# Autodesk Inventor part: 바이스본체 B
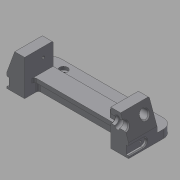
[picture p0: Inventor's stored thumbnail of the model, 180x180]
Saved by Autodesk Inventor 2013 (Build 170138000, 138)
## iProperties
Created: 2017-04
Part Number: 바이스본체 B
Material: 일반
Document SubType Name: Modeling
Designer: mduedu
Density: 1 g/cm^3
Mass: 119.615 g
Surface Area: 275.767 cm^2
Volume: 119.615 cm^3
Author: mduedu
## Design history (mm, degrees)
sketch "스케치1"
  geometry: L1 (-75, 0)-(75, 0); L2 (-75, 0)-(-75, 17); L3 (-53, 17)-(53, 17); L4 (75, 17)-(75, 0); L5 (-75, 17)-(-65.173, 44); L6 (-65.173, 44)-(-53, 44); L7 (-53, 44)-(-53, 17); L8 (0, 0)-(0, 17); L9 (75, 17)-(65.173, 44); L10 (65.173, 44)-(53, 44); L11 (53, 44)-(53, 17); 1 further point
  constraints: 22 end point, 4 perpendicular, 2 horizontal alignment, 2 midpoint, 2 symmetric about line, 1 coincident, 1 collinear, 1 horizontal, 1 vertical
  dimensions: "d0" = 150 distance of L1.start L1.end; "d1" = 17 distance of L1.start L2.end; "d2" = 27 distance of L3.start L6.end; "d3" = 22 distance of L3.start L2.end; "d4" = 70 deg angle of L3 L5; "d54" = 20 deg angle of L9 L4
extrude "돌출1" new body sketch "스케치1" stored distance "d5" = 70; taper "d6" = 0 deg
sketch "스케치2"
  geometry: L1 (0, 70)-(106, 70) reference; L2 (106, 70)-(106, 0) reference; L3 (106, 0)-(0, 0) reference; L4 (0, 47)-(106, 47); L5 (106, 47)-(106, 23); L6 (106, 23)-(0, 23); L7 (0, 23)-(0, 47); L8 (0, 70)-(0, 0) reference; 2 further points
  constraints: 8 end point, 2 parallel, 2 point on line, 1 horizontal, 1 horizontal alignment, 1 midpoint, 1 perpendicular
  dimensions: "d7" = 24 distance between parallel lines of L6 L4
extrude "돌출2" cut sketch "스케치2" stored distance "d9" = 70; taper "d10" = 0 deg
sketch "스케치3"
  geometry: L1 (22, -23)-(128, -23) reference; L2 (128, -47)-(22, -47) reference; L3 (22, -18)-(128, -18); L4 (128, -52)-(22, -52); L5 (22, -18)-(22, -52); L6 (128, -18)-(128, -52); 1 further point
  constraints: 8 end point, 3 parallel, 2 point on line, 1 perpendicular
  dimensions: "d11" = 5 distance between parallel lines of L3 L1; "d12" = 5 distance between parallel lines of L4 L2
extrude "돌출3" cut sketch "스케치3" distance "d13" = 12; taper "d14" = 0 deg
fillet "모깎기1" dims "d15" = 3, "d16" = 3
sketch "스케치4"
  geometry: L1 (103, 23)-(3, 23) reference; L2 (0, 26)-(0, 0) reference; L3 (106, 0)-(0, 0) reference; L4 (106, 26)-(106, 0) reference; L5 (96, 0)-(90, 0); L6 (90, 0)-(90, 19.5); L7 (96, 19.5)-(96, 0); L8 (90, 19.5)-(96, 19.5); A1 r 3 centre (3, 26) between (0, 26) and (3, 23) reference; A2 r 3 centre (103, 26) between (103, 23) and (106, 26) reference; 1 further point
  constraints: 8 end point, 2 perpendicular, 1 horizontal, 1 parallel, 1 point on line
  dimensions: "d17" = 10 distance between parallel lines of L7 L4; "d18" = 6 distance between parallel lines of L7 L6; "d27" = 3.5 distance between parallel lines of L8 L1
extrude "돌출4" join sketch "스케치4" distance "d19" = 12; taper "d20" = 0 deg
chamfer "모따기1" distance "d21" = 3; stored, may be unused: second distance "d22" = 2, angle "d23" = 45 deg
chamfer "모따기2" distance "d24" = 3; stored, may be unused: second distance "d25" = 2, angle "d26" = 45 deg
sketch "스케치5"
  geometry: L1 (-15.5, 35.8)-(-15.5, -25.8) reference; L2 (19.5, 0)-(0, 0) reference; C1 r 6.5 at (9.5, 15); 1 further point
  constraints: 1 centre point
  dimensions: "d28" = 13 diameter of C1; "d30" = 15 distance from line of C1.centre L2; "d31" = 25 distance from line of C1.centre L1
extrude "돌출5" cut sketch "스케치5" stored distance "d32" = 12; taper "d33" = 0 deg
sketch "스케치6"
  geometry: C1 r 5 at (-10, 15); C2 r 5 at (-60, 15); A1 r 6.5 centre (-10, 15) between (-15.766, 12) and (-4.234, 12) reference; A2 r 6.5 centre (-60, 15) between (-65.766, 12) and (-54.234, 12) reference; 1 further point
  constraints: 2 centre point, 2 coincident
  dimensions: "d34" = 10 diameter of C1; "d35" = 10 diameter of C2 (= d34)
extrude "돌출6" cut sketch "스케치6" stored distance "d36" = 12; taper "d37" = 0 deg
chamfer "모따기3" distance "d38" = 1; stored, may be unused: second distance "d39" = 2, angle "d40" = 45 deg
chamfer "모따기4" distance "d41" = 1; stored, may be unused: second distance "d42" = 2, angle "d43" = 45 deg
sketch "스케치7"
  geometry: L1 (-35, 35.8)-(-35, -25.8) reference; L2 (-70, 0)-(0, 0) reference; C1 r 5 at (-35, 15); 1 further point
  constraints: 1 centre point, 1 point on line
  dimensions: "d44" = 10 diameter of C1; "d45" = 15 distance from line of C1.centre L2
extrude "돌출7" cut sketch "스케치7" stored distance "d46" = 12; taper "d47" = 0 deg
chamfer "모따기5" distance "d48" = 1; stored, may be unused: second distance "d49" = 2, angle "d50" = 45 deg
node "작업축1"
sketch "스케치8"
  geometry: L1 (-105, 32)-(105, 32) reference; L2 (58, 32)-(64, 32); L3 (64, 32)-(64, 40); L4 (64, 40)-(58, 40); L5 (58, 40)-(58, 32); L6 (53, 38)-(53, 26) reference; 1 further point
  constraints: 8 end point, 2 parallel, 1 horizontal, 1 perpendicular, 1 point on line
  dimensions: "d51" = 5 distance from line of L6 L2.start; "d52" = 6 distance of L3.end L4.end; "d53" = 16 diameter of L4 L1
revolve "회전1" sketch "스케치8" stored, may be unused: angle "d55" = 90 deg
fillet "모깎기2"
chamfer "모따기6" distance "d56" = 1; stored, may be unused: second distance "d57" = 2, angle "d58" = 45 deg
sketch "스케치9"
  geometry: L1 (17.5, 3)-(52.5, 3); L2 (52.5, 13)-(17.5, 13); L3 (70, 0)-(0, 0) reference; L4 (17.5, 8)-(52.5, 8); A1 r 5 centre (17.5, 8) between (17.5, 13) and (17.5, 3); A2 r 5 centre (52.5, 8) between (52.5, 3) and (52.5, 13); 3 further points
  constraints: 6 end point, 4 point on circle, 3 tangent, 2 centre point, 2 midpoint, 2 parallel, 1 horizontal, 1 vertical alignment
  dimensions: "d59" = 35 distance of L4.start L4.end; "d61" = 5 radius of A2; "d62" = 8 distance between parallel lines of L3 L4
extrude "돌출8" cut sketch "스케치9" distance "d63" = 3; taper "d64" = 0 deg
chamfer "모따기7" distance "d65" = 1; stored, may be unused: second distance "d66" = 2, angle "d67" = 45 deg
chamfer "모따기8" distance "d68" = 1; stored, may be unused: second distance "d69" = 2, angle "d70" = 45 deg
feature "분할1"
sketch "스케치10"
  geometry: A1 r 5 centre (0, 0) between (0, 5) and (0, -5) reference; 1 further point
  constraints: 1 coincident
hole "구멍1" sketch "스케치10" at (0, 0) diameter "d71" = 2.459; stored, may be unused: countersink angle "d75" = 90 deg, drill point angle "d77" = 120 deg; dims "d72" = 4.5, "d73" = 4, "d74" = 2, "d76" = 6
sketch "스케치11"
  geometry: L1 (0, 0)-(0, 27) reference; L2 (0, 27)-(-35, 27) reference; 2 further points
  dimensions: "d78" = 12 distance from line of point (-12, 15.5) L1; "d79" = 11.5 distance from line of point (-12, 15.5) L2
hole "구멍2" sketch "스케치11" at (-12, 15.5) diameter "d80" = 3.242; stored, may be unused: countersink angle "d84" = 90 deg, drill point angle "d86" = 120 deg; dims "d81" = 6, "d82" = 4, "d83" = 2, "d85" = 8
sketch "스케치12"
  geometry: L1 (-75, -35)-(-75, 0) reference; L2 (75, -35)-(75, 0) reference; L3 (75, -35)-(-75, -35); L4 (-75, -35)-(-75, -55); L5 (-75, -55)-(75, -55); L6 (75, -55)-(75, -35); 1 further point
  constraints: 8 end point, 2 parallel, 1 horizontal, 1 perpendicular, 1 point on line
  dimensions: "d87" = 20 distance of L3.end L4.end; "d89" = 150 distance of L4.end L5.end (derived)
extrude "돌출9" join sketch "스케치12" distance "d90" = 10; taper "d91" = 0 deg
sketch "스케치13"
  geometry: L1 (-75, 55)-(-75, 35) reference; L2 (75, 35)-(75, 55) reference; L3 (-75, 45)-(75, 45); 3 further points
  constraints: 2 end point, 2 midpoint, 2 point on line
  dimensions: "d92" = 50 horizontal distance of point (-50, 45) point (0, 0); "d93" = 100 distance of point (50, 45) point (-50, 45)
fillet "모깎기3" dims "d94" = 12
chamfer "모따기9" distance "d95" = 1; stored, may be unused: second distance "d96" = 2, angle "d97" = 45 deg
hole "구멍3" sketch "스케치13" diameter "d98" = 4.134; stored, may be unused: countersink angle "d102" = 90 deg, drill point angle "d104" = 118 deg; dims "d99" = 6, "d100" = 10, "d101" = 4, "d103" = 8
node "솔리드1"
mirror "대칭1"
mirror "대칭2"
mirror "대칭3"
mirror "대칭4"
node "투영된 루프1"
